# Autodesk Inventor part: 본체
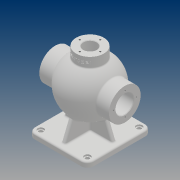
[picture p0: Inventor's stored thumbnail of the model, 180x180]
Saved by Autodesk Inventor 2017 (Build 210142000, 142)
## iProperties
Part Number: 본체
Material: 일반
Document SubType Name: Modeling
Designer: 19
Density: 1 g/cm^3
Appearance: 기본값
Mass: 557.04 g
Surface Area: 1153.86 cm^2
Volume: 557.04 cm^3
Author: 19
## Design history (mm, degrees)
sketch "스케치1"
  geometry: L1 (-53, 0)-(53, 0); A1 r 53 centre (0, 0) between (53, 0) and (-53, 0); 1 further point
  constraints: 2 end point, 2 point on circle, 1 centre point, 1 coincident, 1 horizontal, 1 midpoint
  dimensions: "d0" = 106 diameter of A1
revolve "회전1" sketch "스케치1" stored, may be unused: angle "d1" = 90 deg
sketch "스케치2"
  geometry: L1 (-43, 0)-(43, 0); A1 r 43 centre (0, 0) between (43, 0) and (-43, 0); 1 further point
  constraints: 2 end point, 2 point on circle, 1 centre point, 1 coincident, 1 horizontal, 1 midpoint
  dimensions: "d2" = 86 diameter of A1
revolve "회전2" sketch "스케치2" stored, may be unused: angle "d3" = 90 deg
node "작업 평면1"
sketch "스케치3"
  geometry: L1 (57.5, -62.5)-(-57.5, -62.5); L2 (-57.5, -62.5)-(-57.5, 62.5); L3 (-57.5, 62.5)-(57.5, 62.5); L4 (57.5, 62.5)-(57.5, -62.5); L5 (57.5, -62.5)-(-57.5, 62.5); L6 (-57.5, -62.5)-(57.5, 62.5); 1 further point
  constraints: 12 end point, 2 midpoint, 2 parallel, 1 horizontal, 1 perpendicular
  dimensions: "d5" = 125 distance of L1.end L2.end; "d6" = 115 distance of L2.end L3.end
extrude "돌출1" join sketch "스케치3" distance "d7" = 10; taper "d8" = 0 deg
sketch "스케치7"
  geometry: L1 (4, -52.5)-(-4, -52.5); L2 (-4, -52.5)-(-4, 52.5); L3 (-4, 52.5)-(4, 52.5); L4 (4, 52.5)-(4, -52.5); L5 (4, -52.5)-(-4, 52.5); L6 (-4, -52.5)-(4, 52.5); L7 (47.5, -4)-(-47.5, -4); L8 (-47.5, -4)-(-47.5, 4); L9 (-47.5, 4)-(47.5, 4); L10 (47.5, 4)-(47.5, -4); L11 (47.5, -4)-(-47.5, 4); L12 (-47.5, -4)-(47.5, 4); L13 (57.5, -62.5)-(-57.5, -62.5) reference; L14 (57.5, 62.5)-(57.5, -62.5) reference; 1 further point
  constraints: 24 end point, 4 midpoint, 4 parallel, 2 horizontal, 2 perpendicular
  dimensions: "d14" = 8 distance of L2.end L3.end; "d15" = 8 distance of L7.end L8.end; "d16" = 10 distance between parallel lines of L13 L1; "d17" = 10 distance between parallel lines of L14 L10
extrude "돌출2" join sketch "스케치7" stored distance "d18" = 10; taper "d19" = 0 deg
feature "면 기울기1" dims angle "d20" = 22 deg
feature "면 기울기2" dims angle "d21" = 22 deg
feature "면 기울기3" dims angle "d22" = 22 deg
feature "면 기울기4" dims angle "d23" = 22 deg
node "작업 평면2"
sketch "스케치9"
  geometry: C1 r 31 at (0, 0); 1 further point
  constraints: 1 centre point, 1 coincident
  dimensions: "d25" = 62 diameter of C1
extrude "돌출3" join sketch "스케치9" stored distance "d26" = 10; taper "d27" = 0 deg
node "작업 평면3"
sketch "스케치10"
  geometry: C1 r 31 at (0, 0); 1 further point
  constraints: 1 centre point, 1 coincident
  dimensions: "d29" = 62 diameter of C1
extrude "돌출4" join sketch "스케치10" stored distance "d30" = 10; taper "d31" = 0 deg
node "작업 평면4"
sketch "스케치11"
  geometry: C1 r 27 at (0, 0); 1 further point
  constraints: 1 centre point, 1 coincident
  dimensions: "d33" = 54 diameter of C1
extrude "돌출5" join sketch "스케치11" stored distance "d34" = 10; taper "d35" = 0 deg
sketch "스케치13"
  geometry: C1 r 17.5 at (0, 0); 1 further point
  constraints: 1 centre point, 1 coincident
  dimensions: "d36" = 35 diameter of C1
extrude "돌출6" cut sketch "스케치13" stored distance "d37" = 10; taper "d38" = 0 deg
node "작업 평면5"
sketch "스케치15"
  geometry: C1 r 13 at (0, 0); 1 further point
  constraints: 1 centre point, 1 coincident
  dimensions: "d43" = 26 diameter of C1
extrude "돌출8" cut sketch "스케치15" distance "d44" = 50; taper "d45" = 0 deg
sketch "스케치17"
  geometry: 2 further points
  constraints: 1 vertical alignment
  dimensions: "d57" = 20 distance of point (0, 0) point (0, 20)
hole "구멍2" sketch "스케치17" at (0, 20) diameter "d58" = 3.242; stored, may be unused: countersink angle "d62" = 90 deg, drill point angle "d64" = 118 deg; dims "d59" = 9, "d60" = 4, "d61" = 2, "d63" = 11
fillet "모깎기1" dims "d79" = 12
chamfer "모따기1" distance "d80" = 1; stored, may be unused: second distance "d81" = 2, angle "d82" = 45 deg
fillet "모깎기2" dims "d83" = 3
fillet "모깎기3" dims "d84" = 3
fillet "모깎기4" dims "d85" = 3
sketch "스케치20"
  geometry: L1 (-45.5, -62.5)-(45.5, -62.5) reference; L2 (-57.5, 50.5)-(-57.5, -50.5) reference; 2 further points
  dimensions: "d86" = 12 distance from line of L1 point (-45.5, -50.5); "d87" = 12 distance from line of L2 point (-45.5, -50.5)
hole "구멍4" sketch "스케치20" at (-45.5, -50.5) diameter "d88" = 8; stored, may be unused: countersink angle "d92" = 90 deg, drill point angle "d94" = 118 deg; dims "d89" = 12, "d90" = 12, "d91" = 3, "d93" = 15
node "작업 평면6"
node "작업 평면8"
sketch "스케치23"
  geometry: C1 r 18.5 at (0, 0); 1 further point
  constraints: 1 centre point, 1 coincident
  dimensions: "d109" = 37 diameter of C1
extrude "돌출9" cut sketch "스케치23" distance "d110" = 1.75; taper "d111" = 0 deg
sketch "스케치24"
  geometry: 2 further points
  constraints: 1 horizontal alignment
  dimensions: "d112" = 24 distance of point (0, 0) point (24, 0)
hole "구멍5" sketch "스케치24" at (24, 0) diameter "d113" = 3.242; stored, may be unused: countersink angle "d117" = 90 deg, drill point angle "d119" = 118 deg; dims "d114" = 16, "d115" = 12, "d116" = 3, "d118" = 19
sketch "스케치25"
  geometry: 2 further points
  constraints: 1 horizontal alignment
  dimensions: "d123" = 22.5 distance of point (0, 0) point (-22.5, 0)
hole "구멍6" sketch "스케치25" at (-22.5, 0) diameter "d124" = 3.242; stored, may be unused: countersink angle "d128" = 90 deg, drill point angle "d130" = 118 deg; dims "d125" = 12, "d126" = 12, "d127" = 3, "d129" = 15
node "작업 평면9"
sketch "스케치26"
  geometry: L1 (27, 65)-(-27, 65) reference; L2 (-27, 65)-(-27, 47.286) reference; 2 further points
  constraints: 1 other
  dimensions: "d135" = 27 distance from line of L2 point (0, 55); "d136" = 10 distance from line of L1 point (0, 55)
feature "엠보싱2" sketch "스케치26" dims "d0" = 106, "d137" = 0.5, "d138" = 0
node "솔리드1"
pattern_circular "원형 패턴2" dims angle "d66" = 360 deg
pattern_linear "직사각형 패턴1" dims "d97" = 101, "d100" = 91
pattern_circular "원형 패턴4" dims angle "d121" = 360 deg
pattern_circular "원형 패턴5" dims angle "d132" = 360 deg
other parameters: "d4" = -85, "d24" = 68, "d28" = -68, "d39" = -16, "d108" = -16
